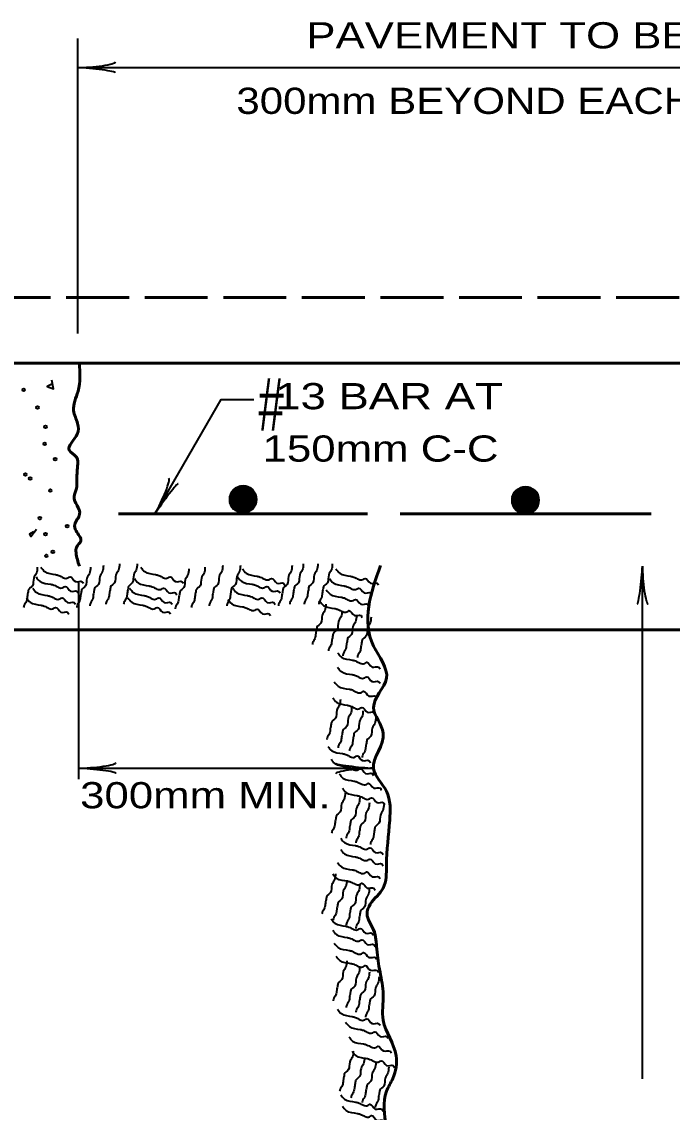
# Model space of a CAD drawing. Extents: x -617 to 238, y 23 to 567.
# Drawn here: x -288.2 to -228.6, y 332.5 to 432.4 of the extents above; entities that cross this region are included whole.
import ezdxf
from ezdxf.enums import TextEntityAlignment as Align

# ---------------------------------------------------------------- set-up
doc = ezdxf.new("R2010")
doc.units = 0
doc.header["$LTSCALE"] = 0.96
doc.linetypes.add('LONG_DASHED', pattern=[7.5, 6, -1.5])
doc.layers.add('1', color=7, linetype='Continuous', lineweight=40)

msp = doc.modelspace()

# ---------------------------------------------------------------- linework, layer by layer
at = {"layer": '1', "lineweight": 35}
for p, q in [((-283.0353, 403.8593), (-283.0353, 430.8593)), ((-283.0353, 428.2004), (-176.2353, 428.2004)), ((-231.291, 335.5737), (-231.291, 382.5379)), ((-282.9653, 381.0289), (-282.9653, 363.0289)), ((-282.9653, 364.0386), (-255.9524, 364.0386))]:
    msp.add_line(p, q, dxfattribs=at)
at = {"layer": '1', "linetype": 'LONG_DASHED', "lineweight": 53}
msp.add_line((-327.291, 407.1379), (-135.291, 407.1379), dxfattribs=at)
at = {"layer": '1', "lineweight": 53}
for p, q in [((-327.291, 401.1379), (-135.291, 401.1379)), ((-279.291, 387.3379), (-256.4909, 387.3379)), ((-253.4807, 387.3379), (-230.4889, 387.3379)), ((-325.834, 376.7054), (-133.834, 376.7054))]:
    msp.add_line(p, q, dxfattribs=at)
at = {"layer": '1', "lineweight": 35}
for points in [[(-285.4021, 399.2122), (-285.8453, 398.9906), (-285.2544, 398.769), (-285.4021, 399.5816)], [(-275.9539, 387.3379), (-269.9059, 397.8133), (-266.9059, 397.8133)], [(-287.1011, 385.694), (-287.4705, 385.4724), (-287.3227, 385.2507), (-286.8056, 385.9156)]]:
    msp.add_lwpolyline(points, dxfattribs=at)
for centre in [(-287.9876, 398.6951), (-286.7318, 397.0699), (-285.9931, 395.2971), (-286.0669, 393.7458), (-285.1066, 392.3422), (-287.8398, 390.9387), (-287.3966, 390.5694), (-285.5498, 389.4613), (-286.5102, 386.9497), (-285.9931, 385.4723), (-283.9986, 386.211), (-285.9192, 383.4778), (-285.3282, 383.8472)]:
    msp.add_circle(centre, 0.12, dxfattribs=at)
at = {"layer": '1', "lineweight": 53}
for centre, radius in [((-267.8827, 388.6544), 1.2), ((-267.8877, 388.6321), 1.0988), ((-267.8901, 388.7014), 1.032), ((-267.8877, 388.6717), 0.9607), ((-267.8753, 388.6396), 0.884), ((-242.0039, 388.5752), 1.2), ((-242.0089, 388.5529), 1.0988), ((-242.0113, 388.6222), 1.032), ((-242.0089, 388.5925), 0.9607), ((-267.863, 388.6272), 0.8128), ((-267.8505, 388.6297), 0.7422), ((-267.8432, 388.6396), 0.6733), ((-267.8357, 388.6668), 0.6068), ((-267.8358, 388.6693), 0.5282), ((-267.8234, 388.6741), 0.4508), ((-267.8259, 388.6741), 0.3792), ((-267.8308, 388.694), 0.3052), ((-267.8283, 388.6866), 0.2278), ((-267.8258, 388.694), 0.166), ((-267.8159, 388.6841), 0.1015), ((-267.8159, 388.6866), 0.0427), ((-241.9965, 388.5604), 0.884), ((-241.9841, 388.548), 0.8128), ((-241.9718, 388.5505), 0.7422), ((-241.9644, 388.5604), 0.6733), ((-241.9569, 388.5876), 0.6068), ((-241.957, 388.5901), 0.5282), ((-241.9446, 388.595), 0.4508), ((-241.9471, 388.595), 0.3792), ((-241.952, 388.6148), 0.3052), ((-241.9495, 388.6073), 0.2278), ((-241.947, 388.6148), 0.166), ((-241.9371, 388.6048), 0.1015), ((-241.9372, 388.6073), 0.0427)]:
    msp.add_circle(centre, radius, dxfattribs=at)
at = {"layer": '1'}
for centre, major_axis, ratio, start_param, end_param in [((-281.7259, 428.532), (-2.1428, -0.1874), 0.122415, 0.8963533, 3.1415927), ((-281.6907, 427.9465), (2.1077, -0.2108), 0.07063, 6.2823074, 8.5597026), ((-275.5863, 388.6377), (-0.9091, -1.9494), 0.122415, 0.8963533, 3.1415927), ((-275.0617, 388.3754), (1.2364, 1.72), 0.07063, 6.2823074, 8.5597026), ((-231.5449, 381.1933), (-0.2108, -2.1077), 0.07063, 6.2823074, 8.5597026), ((-231.5449, 381.1933), (-0.2108, -2.1077), 0.07063, 6.2823074, 8.5597026), ((-230.9594, 381.2285), (-0.1874, 2.1428), 0.122415, 0.8963533, 3.1415927), ((-230.9594, 381.2285), (-0.1874, 2.1428), 0.122415, 0.8963533, 3.1415927), ((-281.6559, 364.3702), (-2.1428, -0.1874), 0.122415, 0.8963533, 3.1415927), ((-281.6559, 364.3702), (-2.1428, -0.1874), 0.122415, 0.8963533, 3.1415927), ((-281.6207, 363.7847), (2.1077, -0.2108), 0.07063, 6.2823074, 8.5597026), ((-281.6207, 363.7847), (2.1077, -0.2108), 0.07063, 6.2823074, 8.5597026), ((-257.2618, 363.707), (2.1428, 0.1874), 0.122415, 0.8963533, 3.1415927), ((-257.297, 364.2925), (2.1077, -0.2108), 0.07063, 3.1407148, 5.41811)]:
    msp.add_ellipse(centre, major_axis=major_axis, ratio=ratio, start_param=start_param, end_param=end_param, dxfattribs=at)
at = {"layer": '1', "lineweight": 53}
for points in [[(-282.8913, 401.1321), (-283.0105, 398.5602), (-283.4168, 396.7873), (-283.0474, 395.6054), (-283.0843, 394.6451), (-283.823, 393.1677), (-283.1582, 392.5398), (-283.0474, 391.6903), (-283.1213, 390.3976), (-283.1582, 389.6589), (-283.3798, 388.9202), (-282.8627, 387.2951), (-283.306, 386.3717), (-283.1952, 385.7808), (-282.7519, 384.8574), (-283.1582, 384.2664), (-283.1952, 383.7863), (-282.891, 382.5379)], [(-255.291, 382.6114), (-255.9281, 375.2243), (-254.7461, 372.2695), (-255.9281, 369.6102), (-255.0416, 367.2463), (-255.9281, 363.9961), (-254.7461, 361.9277), (-254.4506, 359.2684), (-254.7461, 355.1316), (-255.0416, 353.0633), (-256.2235, 351.5858), (-256.519, 350.6994), (-255.9281, 349.222), (-255.6326, 347.4491), (-255.3371, 345.3807), (-255.0416, 343.3124), (-255.0416, 340.9485), (-253.8597, 337.6982), (-254.1552, 335.6299), (-254.7461, 334.4479), (-254.7461, 331.1977), (-254.4506, 327.3564), (-254.7461, 325.879), (-254.7461, 322.6287), (-255.3371, 318.492), (-255.3371, 315.5372), (-256.519, 311.6959), (-255.6326, 309.6275), (-255.9281, 306.9682), (-256.2235, 303.7179), (-255.9281, 301.6495), (-255.6326, 298.1038), (-255.3371, 296.0354), (-255.6326, 293.6716), (-255.6326, 289.8303), (-254.7461, 288.9439), (-255.3371, 284.2162), (-255.3371, 281.5568), (-255.0416, 279.7839), (-255.6326, 276.2382), (-255.0416, 274.7608), (-255.6326, 272.1014), (-255.0416, 270.9195), (-252.6778, 268.5557), (-250.6094, 269.1466), (-248.541, 270.624), (-246.7681, 269.1466), (-244.9953, 268.8511), (-241.154, 268.8511), (-237.3127, 270.3286), (-236.1308, 269.4421), (-231.1076, 269.4421), (-226.6754, 270.0331), (-224.3116, 269.4421), (-219.2884, 270.0331), (-217.5155, 269.7376), (-212.1969, 270.0331), (-211.6059, 269.1466), (-208.0601, 269.7376), (-205.4008, 273.2834), (-205.6963, 275.3517), (-205.9918, 276.5337), (-207.7646, 282.1478), (-205.4008, 285.9891), (-206.8782, 289.2393), (-206.8782, 290.4213), (-205.6963, 292.4896), (-206.2872, 295.7399), (-205.4008, 297.2173), (-204.2189, 300.1721), (-205.9918, 305.1953), (-205.9918, 306.9682), (-205.6963, 309.0366), (-206.5827, 311.6959), (-206.2872, 313.4688), (-206.5827, 316.7191), (-207.7646, 320.8558), (-205.9918, 324.1061), (-205.6963, 326.7654), (-205.4008, 331.1977), (-205.6963, 333.5615), (-206.5827, 335.6299), (-206.5827, 337.4028), (-206.2872, 340.9485), (-207.4692, 344.4943), (-207.7646, 347.7446), (-205.6963, 350.9949), (-206.5827, 353.3587), (-206.8782, 354.8361), (-205.4008, 358.3819), (-206.5827, 361.0412), (-206.5827, 366.0644), (-206.2872, 367.8373), (-205.9918, 369.6102), (-207.1737, 372.8605), (-207.4692, 374.6334), (-207.291, 382.6114)]]:
    msp.add_spline(points, degree=3, dxfattribs=at)
at = {"layer": '1'}
for points in [[(-280.6864, 382.5946), (-280.789, 382.0127), (-281.0114, 381.6019), (-281.1397, 380.8743), (-281.5078, 380.4892), (-281.5333, 380.3438), (-281.6103, 379.9072), (-281.6872, 379.4707), (-281.9098, 379.06), (-281.9355, 378.9144)], [(-279.209, 382.7423), (-279.3116, 382.1604), (-279.534, 381.7496), (-279.6623, 381.022), (-280.0304, 380.6369), (-280.0559, 380.4915), (-280.1329, 380.0549), (-280.2098, 379.6184), (-280.4324, 379.2077), (-280.4581, 379.0621)], [(-277.5839, 382.7423), (-277.6865, 382.1604), (-277.9089, 381.7496), (-278.0372, 381.022), (-278.4053, 380.6369), (-278.4308, 380.4915), (-278.5078, 380.0549), (-278.5847, 379.6184), (-278.8073, 379.2077), (-278.833, 379.0621)], [(-269.7536, 382.5946), (-269.8562, 382.0127), (-270.0786, 381.6019), (-270.2069, 380.8743), (-270.575, 380.4892), (-270.6005, 380.3438), (-270.6775, 379.9072), (-270.7544, 379.4707), (-270.977, 379.06), (-271.0027, 378.9144)], [(-268.1285, 382.5946), (-268.2311, 382.0127), (-268.4535, 381.6019), (-268.5818, 380.8743), (-268.9499, 380.4892), (-268.9754, 380.3438), (-269.0524, 379.9072), (-269.1293, 379.4707), (-269.3519, 379.06), (-269.3776, 378.9144)], [(-263.4008, 382.5946), (-263.5034, 382.0127), (-263.7258, 381.6019), (-263.8541, 380.8743), (-264.2222, 380.4892), (-264.2477, 380.3438), (-264.3247, 379.9072), (-264.4016, 379.4707), (-264.6242, 379.06), (-264.6499, 378.9144)], [(-262.3666, 382.7423), (-262.4692, 382.1604), (-262.6916, 381.7496), (-262.8199, 381.022), (-263.188, 380.6369), (-263.2135, 380.4915), (-263.2905, 380.0549), (-263.3674, 379.6184), (-263.59, 379.2077), (-263.6157, 379.0621)], [(-261.0369, 382.7423), (-261.1395, 382.1604), (-261.3619, 381.7496), (-261.4902, 381.022), (-261.8583, 380.6369), (-261.8838, 380.4915), (-261.9608, 380.0549), (-262.0377, 379.6184), (-262.2603, 379.2077), (-262.286, 379.0621)], [(-259.7073, 382.7423), (-259.8099, 382.1604), (-260.0323, 381.7496), (-260.1606, 381.022), (-260.5287, 380.6369), (-260.5542, 380.4915), (-260.6312, 380.0549), (-260.7081, 379.6184), (-260.9307, 379.2077), (-260.9564, 379.0621)], [(-286.7438, 382.4468), (-286.8464, 381.8649), (-287.0688, 381.4541), (-287.1971, 380.7265), (-287.5652, 380.3414), (-287.5907, 380.196), (-287.6677, 379.7594), (-287.7446, 379.3229), (-287.9672, 378.9122), (-287.9929, 378.7666)], [(-286.8571, 381.5534), (-286.5056, 381.1531), (-285.5066, 380.8855), (-285.2212, 380.8091), (-284.365, 380.5796), (-284.184, 380.6841), (-283.6895, 380.2458), (-283.0806, 380.2354), (-282.9761, 380.0546)], [(-286.4139, 382.4398), (-286.0624, 382.0395), (-285.0634, 381.7719), (-284.778, 381.6955), (-283.9218, 381.466), (-283.7408, 381.5705), (-283.2463, 381.1322), (-282.6374, 381.1218), (-282.5329, 380.941)], [(-281.8684, 382.4468), (-281.971, 381.8649), (-282.1934, 381.4541), (-282.3217, 380.7265), (-282.6898, 380.3414), (-282.7153, 380.196), (-282.7923, 379.7594), (-282.8692, 379.3229), (-283.0918, 378.9122), (-283.1175, 378.7666)], [(-277.254, 382.4397), (-276.9025, 382.0394), (-275.9035, 381.7718), (-275.6181, 381.6954), (-274.7619, 381.4659), (-274.5809, 381.5704), (-274.0864, 381.1321), (-273.4775, 381.1217), (-273.373, 380.9409)], [(-272.8562, 382.2991), (-272.9588, 381.7172), (-273.1812, 381.3064), (-273.3095, 380.5788), (-273.6776, 380.1937), (-273.7031, 380.0483), (-273.7801, 379.6117), (-273.857, 379.1752), (-274.0796, 378.7645), (-274.1053, 378.6189)], [(-271.3788, 382.4468), (-271.4814, 381.8649), (-271.7038, 381.4541), (-271.8321, 380.7265), (-272.2002, 380.3414), (-272.2257, 380.196), (-272.3027, 379.7594), (-272.3796, 379.3229), (-272.6022, 378.9122), (-272.6279, 378.7666)], [(-268.3895, 381.5533), (-268.038, 381.153), (-267.039, 380.8854), (-266.7536, 380.809), (-265.8974, 380.5795), (-265.7164, 380.684), (-265.2219, 380.2457), (-264.613, 380.2353), (-264.5085, 380.0545)], [(-267.9463, 382.292), (-267.5948, 381.8917), (-266.5958, 381.6241), (-266.3104, 381.5477), (-265.4542, 381.3182), (-265.2732, 381.4227), (-264.7787, 380.9844), (-264.1698, 380.974), (-264.0653, 380.7932)], [(-259.3774, 382.292), (-259.0259, 381.8917), (-258.0269, 381.6241), (-257.7415, 381.5477), (-256.8853, 381.3182), (-256.7043, 381.4227), (-256.2098, 380.9844), (-255.6009, 380.974), (-255.4964, 380.7932)], [(-287.1526, 380.5192), (-286.8011, 380.1189), (-285.8021, 379.8513), (-285.5167, 379.7749), (-284.6605, 379.5454), (-284.4795, 379.6499), (-283.985, 379.2116), (-283.3761, 379.2012), (-283.2716, 379.0204)], [(-278.2882, 380.5191), (-277.9367, 380.1188), (-276.9377, 379.8512), (-276.6523, 379.7748), (-275.7961, 379.5453), (-275.6151, 379.6498), (-275.1206, 379.2115), (-274.5117, 379.2011), (-274.4072, 379.0203)], [(-277.8449, 381.4055), (-277.4934, 381.0052), (-276.4944, 380.7376), (-276.209, 380.6612), (-275.3528, 380.4317), (-275.1718, 380.5362), (-274.6773, 380.0979), (-274.0684, 380.0875), (-273.9639, 379.9067)], [(-268.8327, 380.5191), (-268.4812, 380.1188), (-267.4822, 379.8512), (-267.1968, 379.7748), (-266.3406, 379.5453), (-266.1596, 379.6498), (-265.6651, 379.2115), (-265.0562, 379.2011), (-264.9517, 379.0203)], [(-259.9683, 381.4056), (-259.6168, 381.0053), (-258.6178, 380.7377), (-258.3324, 380.6613), (-257.4762, 380.4318), (-257.2952, 380.5363), (-256.8007, 380.098), (-256.1918, 380.0876), (-256.0873, 379.9068)], [(-287.7435, 379.6327), (-287.392, 379.2324), (-286.393, 378.9648), (-286.1076, 378.8884), (-285.2514, 378.6589), (-285.0704, 378.7634), (-284.5759, 378.3251), (-283.967, 378.3147), (-283.8625, 378.1339)], [(-278.4359, 379.6326), (-278.0844, 379.2323), (-277.0854, 378.9647), (-276.8, 378.8883), (-275.9438, 378.6588), (-275.7628, 378.7633), (-275.2683, 378.325), (-274.6594, 378.3146), (-274.5549, 378.1338)], [(-269.2759, 379.4849), (-268.9244, 379.0846), (-267.9254, 378.817), (-267.64, 378.7406), (-266.7838, 378.5111), (-266.6028, 378.6156), (-266.1083, 378.1773), (-265.4994, 378.1669), (-265.3949, 377.9861)], [(-260.2638, 380.3714), (-259.9123, 379.9711), (-258.9133, 379.7035), (-258.6279, 379.6271), (-257.7717, 379.3976), (-257.5907, 379.5021), (-257.0962, 379.0638), (-256.4873, 379.0534), (-256.3828, 378.8726)], [(-260.2982, 379.0488), (-260.4008, 378.4669), (-260.6232, 378.0561), (-260.7515, 377.3285), (-261.1196, 376.9434), (-261.1451, 376.798), (-261.2221, 376.3614), (-261.299, 375.9249), (-261.5216, 375.5142), (-261.5473, 375.3686)], [(-260.8548, 379.3372), (-260.5033, 378.9369), (-259.5043, 378.6693), (-259.2189, 378.5929), (-258.3627, 378.3634), (-258.1817, 378.4679), (-257.6872, 378.0296), (-257.0783, 378.0192), (-256.9738, 377.8384)], [(-258.8208, 378.4578), (-258.9234, 377.8759), (-259.1458, 377.4651), (-259.2741, 376.7375), (-259.6422, 376.3524), (-259.6677, 376.207), (-259.7447, 375.7704), (-259.8216, 375.3339), (-260.0442, 374.9232), (-260.0699, 374.7776)], [(-257.4912, 378.0146), (-257.5938, 377.4327), (-257.8162, 377.0219), (-257.9445, 376.2943), (-258.3126, 375.9092), (-258.3381, 375.7638), (-258.4151, 375.3272), (-258.492, 374.8907), (-258.7146, 374.48), (-258.7403, 374.3344)], [(-256.1615, 377.8668), (-256.2641, 377.2849), (-256.4865, 376.8741), (-256.6148, 376.1465), (-256.9829, 375.7614), (-257.0084, 375.616), (-257.0854, 375.1794), (-257.1623, 374.7429), (-257.3849, 374.3322), (-257.4106, 374.1866)], [(-259.2296, 374.6095), (-258.8781, 374.2092), (-257.8791, 373.9416), (-257.5937, 373.8652), (-256.7375, 373.6357), (-256.5565, 373.7402), (-256.062, 373.3019), (-255.4531, 373.2915), (-255.3486, 373.1107)], [(-259.2296, 373.2799), (-258.8781, 372.8796), (-257.8791, 372.612), (-257.5937, 372.5356), (-256.7375, 372.3061), (-256.5565, 372.4106), (-256.062, 371.9723), (-255.4531, 371.9619), (-255.3486, 371.7811)], [(-259.5251, 371.9502), (-259.1736, 371.5499), (-258.1746, 371.2823), (-257.8892, 371.2059), (-257.033, 370.9764), (-256.852, 371.0809), (-256.3575, 370.6426), (-255.7486, 370.6322), (-255.6441, 370.4514)], [(-258.9686, 370.332), (-259.0712, 369.7501), (-259.2936, 369.3393), (-259.4219, 368.6117), (-259.79, 368.2266), (-259.8155, 368.0812), (-259.8925, 367.6446), (-259.9694, 367.2081), (-260.192, 366.7974), (-260.2177, 366.6518)], [(-259.6728, 370.4728), (-259.3213, 370.0725), (-258.3223, 369.8049), (-258.0369, 369.7285), (-257.1807, 369.499), (-256.9997, 369.6035), (-256.5052, 369.1652), (-255.8963, 369.1548), (-255.7918, 368.974)], [(-257.9344, 369.5934), (-258.037, 369.0115), (-258.2594, 368.6007), (-258.3877, 367.8731), (-258.7558, 367.488), (-258.7813, 367.3426), (-258.8583, 366.906), (-258.9352, 366.4695), (-259.1578, 366.0588), (-259.1835, 365.9132)], [(-256.9002, 369.2979), (-257.0028, 368.716), (-257.2252, 368.3052), (-257.3535, 367.5776), (-257.7216, 367.1925), (-257.7471, 367.0471), (-257.8241, 366.6105), (-257.901, 366.174), (-258.1236, 365.7633), (-258.1493, 365.6177)], [(-255.7183, 368.707), (-255.8209, 368.1251), (-256.0433, 367.7143), (-256.1716, 366.9867), (-256.5397, 366.6016), (-256.5652, 366.4562), (-256.6422, 366.0196), (-256.7191, 365.5831), (-256.9417, 365.1724), (-256.9674, 365.0268)], [(-260.116, 366.0405), (-259.7645, 365.6402), (-258.7655, 365.3726), (-258.4801, 365.2962), (-257.6239, 365.0667), (-257.4429, 365.1712), (-256.9484, 364.7329), (-256.3395, 364.7225), (-256.235, 364.5417)], [(-259.8205, 364.8586), (-259.469, 364.4583), (-258.47, 364.1907), (-258.1846, 364.1143), (-257.3284, 363.8848), (-257.1474, 363.9893), (-256.6529, 363.551), (-256.044, 363.5406), (-255.9395, 363.3598)], [(-259.0818, 363.5289), (-258.7303, 363.1286), (-257.7313, 362.861), (-257.4459, 362.7846), (-256.5897, 362.5551), (-256.4087, 362.6596), (-255.9142, 362.2213), (-255.3053, 362.2109), (-255.2008, 362.0301)], [(-258.5254, 361.7631), (-258.628, 361.1812), (-258.8504, 360.7704), (-258.9787, 360.0428), (-259.3468, 359.6577), (-259.3723, 359.5123), (-259.4493, 359.0757), (-259.5262, 358.6392), (-259.7488, 358.2285), (-259.7745, 358.0829)], [(-258.7864, 362.1993), (-258.4349, 361.799), (-257.4359, 361.5314), (-257.1505, 361.455), (-256.2943, 361.2255), (-256.1133, 361.33), (-255.6188, 360.8917), (-255.0099, 360.8813), (-254.9054, 360.7005)], [(-257.1957, 361.3199), (-257.2983, 360.738), (-257.5207, 360.3272), (-257.649, 359.5996), (-258.0171, 359.2145), (-258.0426, 359.0691), (-258.1196, 358.6325), (-258.1965, 358.196), (-258.4191, 357.7853), (-258.4448, 357.6397)], [(-256.3092, 360.8767), (-256.4118, 360.2948), (-256.6342, 359.884), (-256.7625, 359.1564), (-257.1306, 358.7713), (-257.1561, 358.6259), (-257.2331, 358.1893), (-257.31, 357.7528), (-257.5326, 357.3421), (-257.5583, 357.1965)], [(-254.9796, 360.7289), (-255.0822, 360.147), (-255.3046, 359.7362), (-255.4329, 359.0086), (-255.801, 358.6235), (-255.8265, 358.4781), (-255.9035, 358.0415), (-255.9804, 357.605), (-256.203, 357.1943), (-256.2287, 357.0487)], [(-258.9341, 357.6193), (-258.5826, 357.219), (-257.5836, 356.9514), (-257.2982, 356.875), (-256.442, 356.6455), (-256.261, 356.75), (-255.7665, 356.3117), (-255.1576, 356.3013), (-255.0531, 356.1205)], [(-258.9341, 356.5851), (-258.5826, 356.1848), (-257.5836, 355.9172), (-257.2982, 355.8408), (-256.442, 355.6113), (-256.261, 355.7158), (-255.7665, 355.2775), (-255.1576, 355.2671), (-255.0531, 355.0863)], [(-259.2296, 355.4032), (-258.8781, 355.0029), (-257.8791, 354.7353), (-257.5937, 354.6589), (-256.7375, 354.4294), (-256.5565, 354.5339), (-256.062, 354.0956), (-255.4531, 354.0852), (-255.3486, 353.9044)], [(-259.4118, 354.3762), (-259.5144, 353.7943), (-259.7368, 353.3835), (-259.8651, 352.6559), (-260.2332, 352.2708), (-260.2587, 352.1254), (-260.3357, 351.6888), (-260.4126, 351.2523), (-260.6352, 350.8416), (-260.6609, 350.696)], [(-259.6728, 354.369), (-259.3213, 353.9687), (-258.3223, 353.7011), (-258.0369, 353.6247), (-257.1807, 353.3952), (-256.9997, 353.4997), (-256.5052, 353.0614), (-255.8963, 353.051), (-255.7918, 352.8702)], [(-258.3776, 353.7852), (-258.4802, 353.2033), (-258.7026, 352.7925), (-258.8309, 352.0649), (-259.199, 351.6798), (-259.2245, 351.5344), (-259.3015, 351.0978), (-259.3784, 350.6613), (-259.601, 350.2506), (-259.6267, 350.105)], [(-257.1957, 353.342), (-257.2983, 352.7601), (-257.5207, 352.3493), (-257.649, 351.6217), (-258.0171, 351.2366), (-258.0426, 351.0912), (-258.1196, 350.6546), (-258.1965, 350.2181), (-258.4191, 349.8074), (-258.4448, 349.6618)], [(-256.3092, 353.0465), (-256.4118, 352.4646), (-256.6342, 352.0538), (-256.7625, 351.3262), (-257.1306, 350.9411), (-257.1561, 350.7957), (-257.2331, 350.3591), (-257.31, 349.9226), (-257.5326, 349.5119), (-257.5583, 349.3663)], [(-259.8206, 350.2323), (-259.4691, 349.832), (-258.4701, 349.5644), (-258.1847, 349.488), (-257.3285, 349.2585), (-257.1475, 349.363), (-256.653, 348.9247), (-256.0441, 348.9143), (-255.9396, 348.7335)], [(-259.6728, 349.1981), (-259.3213, 348.7978), (-258.3223, 348.5302), (-258.0369, 348.4538), (-257.1807, 348.2243), (-256.9997, 348.3288), (-256.5052, 347.8905), (-255.8963, 347.8801), (-255.7918, 347.6993)], [(-259.5251, 348.0162), (-259.1736, 347.6159), (-258.1746, 347.3483), (-257.8892, 347.2719), (-257.033, 347.0424), (-256.852, 347.1469), (-256.3575, 346.7086), (-255.7486, 346.6982), (-255.6441, 346.5174)], [(-259.3773, 346.8343), (-259.0258, 346.434), (-258.0268, 346.1664), (-257.7414, 346.09), (-256.8852, 345.8605), (-256.7042, 345.965), (-256.2097, 345.5267), (-255.6008, 345.5163), (-255.4963, 345.3355)], [(-258.3776, 346.3981), (-258.4802, 345.8162), (-258.7026, 345.4054), (-258.8309, 344.6778), (-259.199, 344.2927), (-259.2245, 344.1473), (-259.3015, 343.7107), (-259.3784, 343.2742), (-259.601, 342.8635), (-259.6267, 342.7179)], [(-257.1957, 345.8071), (-257.2983, 345.2252), (-257.5207, 344.8144), (-257.649, 344.0868), (-258.0171, 343.7017), (-258.0426, 343.5563), (-258.1196, 343.1197), (-258.1965, 342.6832), (-258.4191, 342.2725), (-258.4448, 342.1269)], [(-256.3092, 345.3639), (-256.4118, 344.782), (-256.6342, 344.3712), (-256.7625, 343.6436), (-257.1306, 343.2585), (-257.1561, 343.1131), (-257.2331, 342.6765), (-257.31, 342.24), (-257.5326, 341.8293), (-257.5583, 341.6837)], [(-255.4228, 344.9207), (-255.5254, 344.3388), (-255.7478, 343.928), (-255.8761, 343.2004), (-256.2442, 342.8153), (-256.2697, 342.6699), (-256.3467, 342.2333), (-256.4236, 341.7968), (-256.6462, 341.3861), (-256.6719, 341.2405)], [(-259.2296, 341.9588), (-258.8781, 341.5585), (-257.8791, 341.2909), (-257.5937, 341.2145), (-256.7375, 340.985), (-256.5565, 341.0895), (-256.062, 340.6512), (-255.4531, 340.6408), (-255.3486, 340.46)], [(-258.4909, 340.7769), (-258.1394, 340.3766), (-257.1404, 340.109), (-256.855, 340.0326), (-255.9988, 339.8031), (-255.8178, 339.9076), (-255.3233, 339.4693), (-254.7144, 339.4589), (-254.6099, 339.2781)], [(-258.1954, 339.4472), (-257.8439, 339.0469), (-256.8449, 338.7793), (-256.5595, 338.7029), (-255.7033, 338.4734), (-255.5223, 338.5779), (-255.0278, 338.1396), (-254.4189, 338.1292), (-254.3144, 337.9484)], [(-257.7866, 338.1247), (-257.8892, 337.5428), (-258.1116, 337.132), (-258.2399, 336.4044), (-258.608, 336.0193), (-258.6335, 335.8739), (-258.7105, 335.4373), (-258.7874, 335.0008), (-259.01, 334.5901), (-259.0357, 334.4445)], [(-257.8999, 338.1175), (-257.5484, 337.7172), (-256.5494, 337.4496), (-256.264, 337.3732), (-255.4078, 337.1437), (-255.2268, 337.2482), (-254.7323, 336.8099), (-254.1234, 336.7995), (-254.0189, 336.6187)], [(-256.7524, 337.5337), (-256.855, 336.9518), (-257.0774, 336.541), (-257.2057, 335.8134), (-257.5738, 335.4283), (-257.5993, 335.2829), (-257.6763, 334.8463), (-257.7532, 334.4098), (-257.9758, 333.9991), (-258.0015, 333.8535)], [(-255.7183, 337.0905), (-255.8209, 336.5086), (-256.0433, 336.0978), (-256.1716, 335.3702), (-256.5397, 334.9851), (-256.5652, 334.8397), (-256.6422, 334.4031), (-256.7191, 333.9666), (-256.9417, 333.5559), (-256.9674, 333.4103)], [(-254.5363, 336.6472), (-254.6389, 336.0653), (-254.8613, 335.6545), (-254.9896, 334.9269), (-255.3577, 334.5418), (-255.3832, 334.3964), (-255.4602, 333.9598), (-255.5371, 333.5233), (-255.7597, 333.1126), (-255.7854, 332.967)], [(-258.9341, 334.1286), (-258.5826, 333.7283), (-257.5836, 333.4607), (-257.2982, 333.3843), (-256.442, 333.1548), (-256.261, 333.2593), (-255.7665, 332.821), (-255.1576, 332.8106), (-255.0531, 332.6298)], [(-258.7864, 333.0944), (-258.4349, 332.6941), (-257.4359, 332.4265), (-257.1505, 332.3501), (-256.2943, 332.1206), (-256.1133, 332.2251), (-255.6188, 331.7868), (-255.0099, 331.7764), (-254.9054, 331.5956)]]:
    msp.add_spline(points, degree=3, dxfattribs=at)

# ---------------------------------------------------------------- texts
for s, height, width, p in [('PAVEMENT TO BE CUT AT LEAST', 2.4, 1.25, (-229.7671, 429.9619)), ('300mm BEYOND EACH EDGE OF TRENCH', 2.4, 1.2, (-229.767, 423.9619)), ('#', 4.8, 0.65, (-265.3204, 394.9643)), ('300mm MIN.', 2.4, 1.25, (-271.3409, 360.3654))]:
    msp.add_text(s, height=height, dxfattribs=dict(at, width=width)).set_placement(p, align=Align.CENTER)
for s, width, p in [(' 13 BAR AT', 1.3, (-266.0987, 396.9145)), ('150mm C-C', 1.25, (-266.0987, 392.1145))]:
    msp.add_text(s, height=2.4, dxfattribs=dict(at, width=width)).set_placement(p)

doc.saveas('drawing.dxf')
